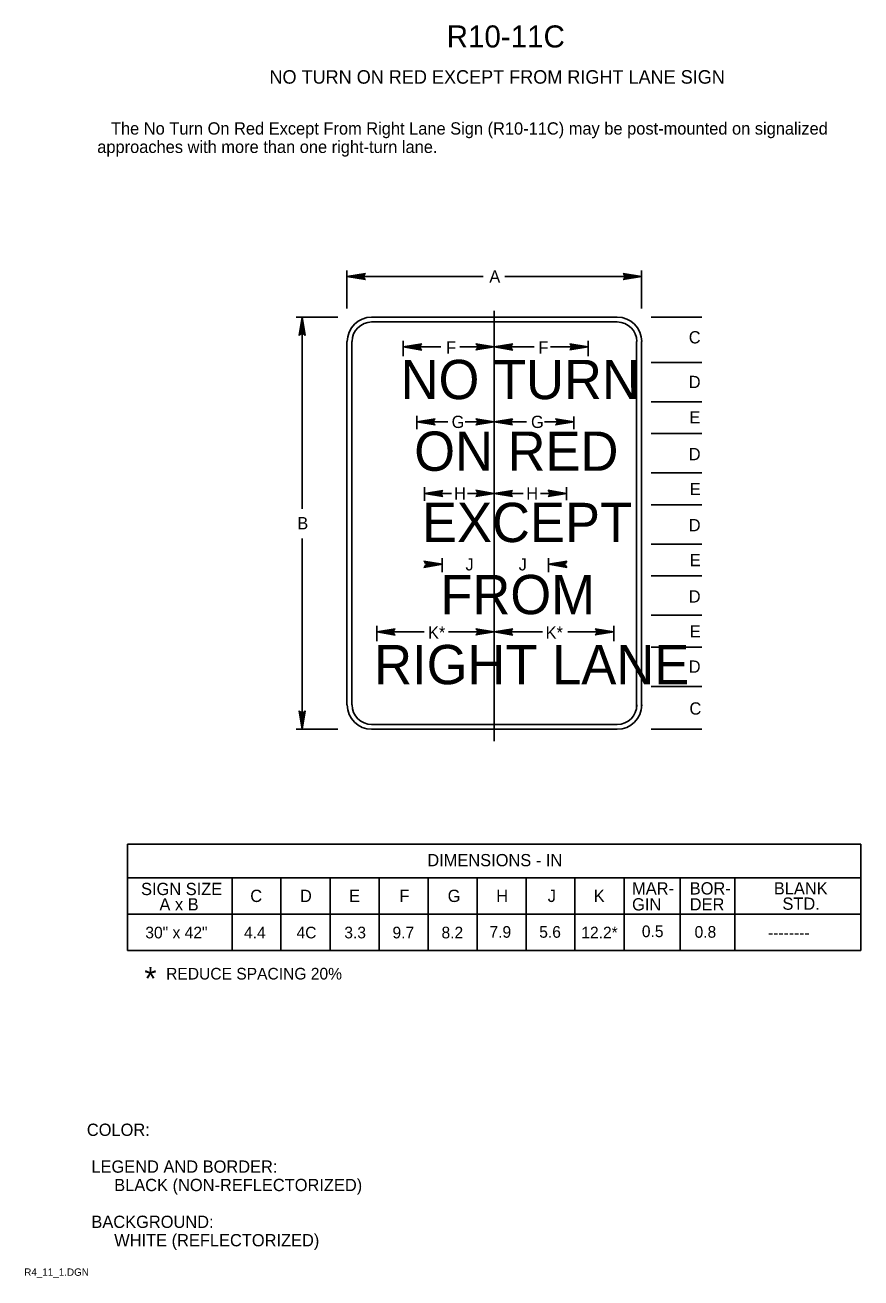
# Model space of a CAD drawing. Extents: x 0.013 to 0.183, y 0.004 to 0.259.
import ezdxf

# ---------------------------------------------------------------- set-up
doc = ezdxf.new("R2010")
doc.units = 0
for name, color, linetype in [('1', 7, 'Continuous'), ('11', 7, 'Continuous'), ('12', 7, 'Continuous'), ('2', 7, 'Continuous'), ('3', 7, 'Continuous')]:
    doc.layers.add(name, color=color, linetype=linetype)

# ---------------------------------------------------------------- blocks, each defined once
blk = doc.blocks.new('RARROW')
at = {"layer": '3'}
for p, q in [((-2.156, 0.285), (-2.2665, 0.384625)), ((-2.2665, 0.384625), (0, 0)), ((0, 0), (-2.2665, -0.379125)), ((-2.156, 0.285), (-2.075625, 0.12075)), ((0, 0), (-2.156, 0.285)), ((-2.14975, -0.2705), (0, 0)), ((-2.075625, 0.12075), (0, 0)), ((0, 0), (-2.074, -0.108)), ((-2.2665, -0.379125), (-2.14975, -0.2705)), ((-2.074, -0.108), (-2.14975, -0.2705))]:
    blk.add_line(p, q, dxfattribs=at)

msp = doc.modelspace()

# ---------------------------------------------------------------- linework, layer by layer
at = {"layer": '11'}
for p, q in [((0.08313, 0.19971), (0.13312, 0.19971)), ((0.07812, 0.12071), (0.07812, 0.19471)), ((0.13812, 0.19471), (0.13812, 0.12006)), ((0.13312, 0.11571), (0.08313, 0.11571))]:
    msp.add_line(p, q, dxfattribs=at)
for centre, start, end in [((0.08317, 0.1947), 90, 180), ((0.13317, 0.1947), 0, 90), ((0.08317, 0.12071), 180, 270), ((0.13317, 0.12071), 270, 0)]:
    msp.add_arc(centre, 0.005, start, end, dxfattribs=at)
at = {"layer": '3'}
for p, q in [((0.07812, 0.20147), (0.07812, 0.20921)), ((0.10587, 0.20796), (0.07812, 0.20796)), ((0.11025, 0.20796), (0.13812, 0.20796)), ((0.13812, 0.20147), (0.13812, 0.20921)), ((0.07625, 0.19971), (0.06775, 0.19971)), ((0.069, 0.16064), (0.069, 0.19971)), ((0.10812, 0.20096), (0.10812, 0.11333)), ((0.14012, 0.19971), (0.15038, 0.19971)), ((0.08313, 0.19871), (0.13312, 0.19871)), ((0.07912, 0.12071), (0.07912, 0.19471)), ((0.0896, 0.19176), (0.0896, 0.19487)), ((0.10812, 0.195), (0.10812, 0.19237)), ((0.10812, 0.19362), (0.11188, 0.19424)), ((0.11168, 0.19406), (0.10812, 0.19362)), ((0.11156, 0.1938), (0.11168, 0.19406)), ((0.11188, 0.19424), (0.11168, 0.19406)), ((0.12368, 0.19409), (0.1235, 0.19425)), ((0.1235, 0.19425), (0.12725, 0.19362)), ((0.12368, 0.19409), (0.12381, 0.19382)), ((0.12725, 0.19362), (0.12368, 0.19409)), ((0.12725, 0.19176), (0.12725, 0.19487)), ((0.13712, 0.19471), (0.13712, 0.12013)), ((0.08966, 0.19362), (0.09721, 0.19362)), ((0.10877, 0.19362), (0.1011, 0.19362)), ((0.10812, 0.19362), (0.11156, 0.1938)), ((0.11313, 0.19362), (0.10812, 0.19362)), ((0.11156, 0.19342), (0.10812, 0.19362)), ((0.10812, 0.19362), (0.11169, 0.19315)), ((0.11188, 0.19299), (0.10812, 0.19362)), ((0.11623, 0.19362), (0.10812, 0.19362)), ((0.11169, 0.19315), (0.11156, 0.19342)), ((0.11169, 0.19315), (0.11188, 0.19299)), ((0.1196, 0.19362), (0.12725, 0.19362)), ((0.12725, 0.19362), (0.1235, 0.193)), ((0.1235, 0.193), (0.12369, 0.19318)), ((0.12369, 0.19318), (0.12725, 0.19362)), ((0.12382, 0.19344), (0.12369, 0.19318)), ((0.12381, 0.19382), (0.12725, 0.19362)), ((0.12725, 0.19362), (0.12382, 0.19344)), ((0.14012, 0.19046), (0.15038, 0.19046)), ((0.14012, 0.18246), (0.15038, 0.18246)), ((0.09234, 0.17685), (0.09234, 0.1796)), ((0.10812, 0.18035), (0.10812, 0.1771)), ((0.12437, 0.17683), (0.12437, 0.17946)), ((0.09865, 0.17835), (0.09277, 0.17835)), ((0.10223, 0.17835), (0.10812, 0.17835)), ((0.11467, 0.17835), (0.10867, 0.17835)), ((0.11837, 0.17835), (0.12418, 0.17835)), ((0.14012, 0.17596), (0.15038, 0.17596)), ((0.14012, 0.16796), (0.15038, 0.16796)), ((0.09393, 0.16228), (0.09393, 0.16503)), ((0.09941, 0.16378), (0.09393, 0.16378)), ((0.10267, 0.16378), (0.10812, 0.16378)), ((0.10812, 0.16516), (0.10812, 0.16253)), ((0.11403, 0.16378), (0.10883, 0.16378)), ((0.11753, 0.16378), (0.12284, 0.16378)), ((0.12284, 0.1624), (0.12284, 0.16503)), ((0.14012, 0.16146), (0.15038, 0.16146)), ((0.069, 0.15457), (0.069, 0.11571)), ((0.14012, 0.15346), (0.15038, 0.15346)), ((0.10812, 0.15133), (0.10812, 0.14808)), ((0.09753, 0.14771), (0.09753, 0.15058)), ((0.11919, 0.14771), (0.11919, 0.15058)), ((0.14012, 0.14696), (0.15038, 0.14696)), ((0.14012, 0.13896), (0.15038, 0.13896)), ((0.08418, 0.13368), (0.08418, 0.1368)), ((0.08418, 0.13555), (0.09385, 0.13555)), ((0.10877, 0.13555), (0.09879, 0.13555)), ((0.10812, 0.13692), (0.10812, 0.1343)), ((0.10812, 0.13555), (0.11188, 0.13617)), ((0.11168, 0.13599), (0.10812, 0.13555)), ((0.10812, 0.13555), (0.11156, 0.13572)), ((0.11313, 0.13555), (0.10812, 0.13555)), ((0.11156, 0.13535), (0.10812, 0.13555)), ((0.10812, 0.13555), (0.11169, 0.13508)), ((0.11188, 0.13492), (0.10812, 0.13555)), ((0.11797, 0.13555), (0.10812, 0.13555)), ((0.11156, 0.13572), (0.11168, 0.13599)), ((0.11169, 0.13508), (0.11156, 0.13535)), ((0.11188, 0.13617), (0.11168, 0.13599)), ((0.12311, 0.13555), (0.13246, 0.13555)), ((0.12889, 0.13601), (0.12871, 0.13618)), ((0.12871, 0.13618), (0.13246, 0.13555)), ((0.13246, 0.13555), (0.12871, 0.13493)), ((0.12889, 0.13601), (0.12902, 0.13574)), ((0.13246, 0.13555), (0.12889, 0.13601)), ((0.1289, 0.1351), (0.13246, 0.13555)), ((0.12903, 0.13537), (0.1289, 0.1351)), ((0.12902, 0.13574), (0.13246, 0.13555)), ((0.13246, 0.13555), (0.12903, 0.13537)), ((0.13246, 0.13368), (0.13246, 0.1368)), ((0.11169, 0.13508), (0.11188, 0.13492)), ((0.12871, 0.13493), (0.1289, 0.1351)), ((0.14012, 0.13246), (0.15038, 0.13246)), ((0.14012, 0.12446), (0.15038, 0.12446)), ((0.07625, 0.11571), (0.06775, 0.11571)), ((0.13312, 0.11671), (0.08313, 0.11671)), ((0.14012, 0.11571), (0.15038, 0.11571)), ((0.03342, 0.09231), (0.03342, 0.07068)), ((0.03342, 0.09231), (0.18283, 0.09231)), ((0.18283, 0.09231), (0.18283, 0.07068)), ((0.03342, 0.08543), (0.15457, 0.08543)), ((0.05471, 0.08543), (0.05471, 0.07068)), ((0.06467, 0.08544), (0.06467, 0.07068)), ((0.07467, 0.08544), (0.07467, 0.07068)), ((0.08467, 0.08544), (0.08467, 0.07068)), ((0.09467, 0.08544), (0.09467, 0.07068)), ((0.10463, 0.08544), (0.10463, 0.07068)), ((0.11466, 0.08544), (0.11466, 0.07068)), ((0.12457, 0.08544), (0.12457, 0.07068)), ((0.13461, 0.08543), (0.13461, 0.07068)), ((0.14599, 0.08543), (0.14599, 0.07068)), ((0.15457, 0.08543), (0.18283, 0.08543)), ((0.15712, 0.08543), (0.15712, 0.07068)), ((0.03342, 0.07806), (0.15457, 0.07806)), ((0.15457, 0.07806), (0.18283, 0.07806)), ((0.03342, 0.07068), (0.15457, 0.07068)), ((0.15457, 0.07068), (0.18283, 0.07068))]:
    msp.add_line(p, q, dxfattribs=at)
for centre, start, end in [((0.08317, 0.1947), 90, 180), ((0.13317, 0.1947), 0, 90), ((0.08317, 0.12071), 180, 270), ((0.13317, 0.12071), 270, 0)]:
    msp.add_arc(centre, 0.004, start, end, dxfattribs=at)

# ---------------------------------------------------------------- block references
at = {"layer": '3', "xscale": 0.0016545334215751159, "yscale": 0.0016366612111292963}
for p, rotation in [((0.07812, 0.20796), 180), ((0.069, 0.19971), 90), ((0.0896, 0.19362), 180), ((0.09234, 0.17835), 180), ((0.10812, 0.17835), 180), ((0.09393, 0.16378), 180), ((0.10812, 0.16378), 180), ((0.11919, 0.14933), 180), ((0.08418, 0.13555), 180), ((0.069, 0.11571), -90)]:
    msp.add_blockref('RARROW', p, dxfattribs=dict(at, rotation=rotation))
for p in [(0.13812, 0.20796), (0.10812, 0.19362), (0.10812, 0.17835), (0.12437, 0.17835), (0.10812, 0.16378), (0.12284, 0.16378), (0.09755, 0.14933), (0.10812, 0.13555)]:
    msp.add_blockref('RARROW', p, dxfattribs=at)

# ---------------------------------------------------------------- texts
at = {"layer": '1'}
for s, height, p in [('R10-11C', 0.0045, (0.09843, 0.25462)), ('NO TURN ON RED EXCEPT FROM RIGHT LANE SIGN', 0.0027503, (0.06233, 0.24725)), ('COLOR:', 0.0025, (0.02513, 0.03288)), (' LEGEND AND BORDER:', 0.0024998, (0.02513, 0.02538)), ('      BLACK (NON-REFLECTORIZED)', 0.0024998, (0.02513, 0.02163)), (' BACKGROUND:', 0.0024998, (0.02513, 0.01413)), ('      WHITE (REFLECTORIZED)', 0.0024998, (0.02513, 0.01038)), ('R4_11_1.DGN', 0.0015, (0.01238, 0.00438))]:
    msp.add_text(s, height=height, dxfattribs=at).set_placement(p)
at = {"layer": '12'}
for s, p in [('NO TURN', (0.08905, 0.18298)), ('ON RED', (0.09182, 0.16838)), ('EXCEPT', (0.0934, 0.15386)), ('FROM', (0.09714, 0.13917)), ('RIGHT LANE', (0.08366, 0.1249))]:
    msp.add_text(s, height=0.008, dxfattribs=at).set_placement(p)
at = {"layer": '2'}
for s, p in [('   The No Turn On Red Except From Right Lane Sign (R10-11C) may be post-mounted on signalized ', (0.02725, 0.23688)), ('approaches with more than one right-turn lane.', (0.02725, 0.23313))]:
    msp.add_text(s, height=0.0024998, dxfattribs=at).set_placement(p)
at = {"layer": '3'}
for s, height, p in [('A', 0.0025, (0.10712, 0.20671)), ('C', 0.0025, (0.14775, 0.19433)), ('F', 0.0025, (0.0983, 0.19225)), ('F', 0.0025, (0.11712, 0.19225)), ('D', 0.0025, (0.14775, 0.18523)), ('G', 0.0025, (0.09944, 0.1771)), ('G', 0.0025, (0.11561, 0.1771)), ('E', 0.0025, (0.14788, 0.17803)), ('D', 0.0025, (0.14775, 0.17053)), ('E', 0.0025, (0.14795, 0.16342)), ('H', 0.0025, (0.09995, 0.16253)), ('H', 0.0025, (0.11465, 0.16253)), ('B', 0.0025, (0.068, 0.15646)), ('D', 0.0025, (0.14775, 0.15606)), ('E', 0.0025, (0.14795, 0.14895)), ('J', 0.0025, (0.10226, 0.14808)), ('J', 0.0025, (0.1131, 0.14808)), ('D', 0.0025, (0.14775, 0.14153)), ('K*', 0.0025, (0.09462, 0.13417)), ('K*', 0.0025, (0.11859, 0.13417)), ('E', 0.0025, (0.14795, 0.13442)), ('D', 0.0025, (0.14775, 0.12724)), ('C', 0.0025, (0.14789, 0.11871)), ('DIMENSIONS - IN', 0.0024998, (0.09449, 0.08781)), ('SIGN SIZE', 0.0025, (0.03617, 0.08194)), ('MAR-', 0.0025, (0.1362, 0.08206)), ('BOR-', 0.0025, (0.14795, 0.08206)), ('BLANK', 0.0025, (0.16508, 0.08207)), ('C', 0.0025, (0.05842, 0.08053)), ('D', 0.0025, (0.06855, 0.08053)), ('E', 0.0025, (0.07855, 0.08053)), ('F', 0.0025, (0.0888, 0.08053)), ('G', 0.0025, (0.09864, 0.08053)), ('H', 0.0025, (0.10853, 0.08053)), ('J', 0.0025, (0.11902, 0.08053)), ('K', 0.0025, (0.12839, 0.08053)), ('A x B', 0.0025, (0.03992, 0.07881)), ('GIN', 0.0025, (0.1362, 0.07881)), ('DER', 0.0025, (0.14795, 0.07881)), ('STD.', 0.0025, (0.16683, 0.07895)), ('30" x 42"', 0.002375, (0.03704, 0.07312)), ('4.4', 0.002375, (0.05715, 0.07312)), ('4C', 0.002375, (0.06784, 0.07312)), ('3.3', 0.002375, (0.07758, 0.07312)), ('9.7', 0.002375, (0.0874, 0.07312)), ('8.2', 0.002375, (0.09738, 0.07312)), ('7.9', 0.002375, (0.10715, 0.07325)), ('5.6', 0.002375, (0.11729, 0.07325)), ('12.2*', 0.002375, (0.12586, 0.07312)), ('0.5', 0.002375, (0.13819, 0.07337)), ('0.8', 0.002375, (0.14893, 0.07325)), ('--------', 0.002375, (0.16391, 0.07312)), ('*', 0.00475, (0.03685, 0.06256)), ('REDUCE SPACING 20%', 0.0023752, (0.04128, 0.06474))]:
    msp.add_text(s, height=height, dxfattribs=at).set_placement(p)

doc.saveas('drawing.dxf')
